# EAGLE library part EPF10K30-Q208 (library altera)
EPF10K30 FLEX 10K family
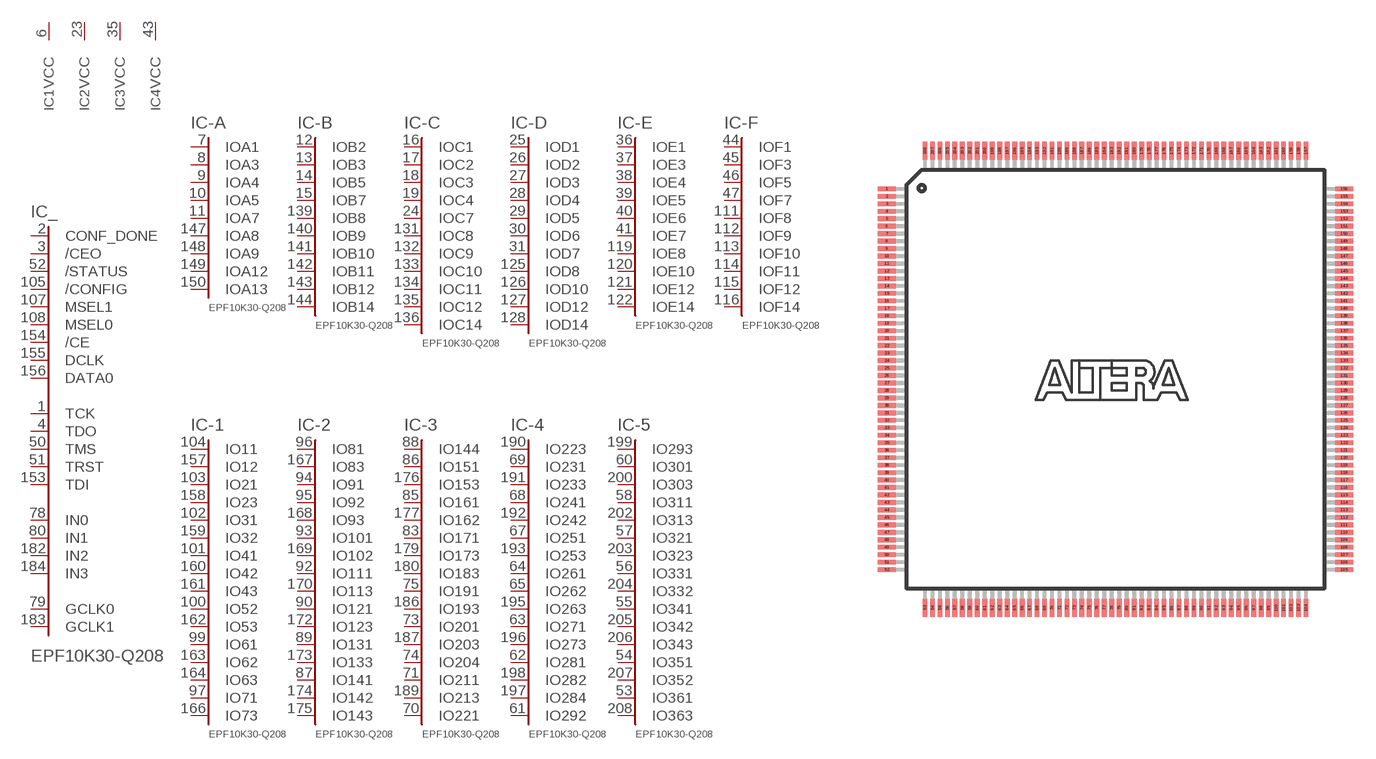
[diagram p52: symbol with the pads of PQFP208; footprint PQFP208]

Designator prefix IC; gates _=100R240C -A=A13-30Q -B=B14-30Q -C=C14-30Q -D=D14-30Q -E=E14-30Q -F=F14-30Q -1=37-30Q -2=143-30Q -3=221-30Q -4=292-30Q -5=363-30Q 1=VCCINT 2=VCCINT 3=VCCINT 4=VCCINT 5=VCCINT 6=VCCINT 7=VCCINT 8=VCCINT 9=VCCINT 10=VCCINT 11=VCCINT 12=VCCINT 13=VCCIO 14=VCCIO 15=VCCIO 16=VCCIO 17=VCCIO 18=VCCIO 19=VCCIO 20=VCCIO 21=VCCIO 22=VCCIO 23=VCCIO 24=VCCIO 25=VCCIO 26=VCCIO 27=GNDINT 28=GNDINT 29=GNDINT 30=GNDINT 31=GNDINT 32=GNDINT 33=GNDINT 34=GNDINT 35=GNDINT 36=GNDIO 37=GNDIO 38=GNDIO 39=GNDIO 40=GNDIO 41=GNDIO 42=GNDIO 43=GNDIO 44=GNDIO 45=GNDIO 46=GNDIO 47=GNDIO

## EPF10K30-Q208 (MPN: EPF10K30EQC208-2N; OC_FARNELL: 1549382; OC_NEWARK: 51R8987)  [PQFP208]
1  _:TCK
2  _:CONF_DONE  in
3  _:/CEO  in
4  _:TDO
5  13:VCCIO  pwr
6  1:VCC  pwr
7  -A:IOA1
8  -A:IOA3
9  -A:IOA4
10  -A:IOA5
11  -A:IOA7
12  -B:IOB2
13  -B:IOB3
14  -B:IOB5
15  -B:IOB7
16  -C:IOC1
17  -C:IOC2
18  -C:IOC3
19  -C:IOC4
20  36:GNDIO  pwr
21  27:GND  pwr
22  14:VCCIO  pwr
23  2:VCC  pwr
24  -C:IOC7
25  -D:IOD1
26  -D:IOD2
27  -D:IOD3
28  -D:IOD4
29  -D:IOD5
30  -D:IOD6
31  -D:IOD7
32  37:GNDIO  pwr
33  28:GND  pwr
34  15:VCCIO  pwr
35  3:VCC  pwr
36  -E:IOE1
37  -E:IOE3
38  -E:IOE4
39  -E:IOE5
40  -E:IOE6
41  -E:IOE7
42  16:VCCIO  pwr
43  4:VCC  pwr
44  -F:IOF1
45  -F:IOF3
46  -F:IOF5
47  -F:IOF7
48  38:GNDIO  pwr
49  29:GND  pwr
50  _:TMS
51  _:TRST
52  _:/STATUS  in
53  -5:IO361
54  -5:IO351
55  -5:IO341
56  -5:IO331
57  -5:IO321
58  -5:IO311
59  39:GNDIO  pwr
60  -5:IO301
61  -4:IO292
62  -4:IO281
63  -4:IO271
64  -4:IO261
65  -4:IO262
66  17:VCCIO  pwr
67  -4:IO251
68  -4:IO241
69  -4:IO231
70  -3:IO221
71  -3:IO211
72  40:GNDIO  pwr
73  -3:IO201
74  -3:IO204
75  -3:IO191
76  5:VCC  pwr
77  6:VCC  pwr
78  _:IN0  in
79  _:GCLK0  in
80  _:IN1  in
81  30:GND  pwr
82  31:GND  pwr
83  -3:IO171
84  18:VCCIO  pwr
85  -3:IO161
86  -3:IO151
87  -2:IO141
88  -3:IO144
89  -2:IO131
90  -2:IO121
91  41:GNDIO  pwr
92  -2:IO111
93  -2:IO101
94  -2:IO91
95  -2:IO92
96  -2:IO81
97  -1:IO71
98  19:VCCIO  pwr
99  -1:IO61
100  -1:IO52
101  -1:IO41
102  -1:IO31
103  -1:IO21
104  -1:IO11
105  _:/CONFIG  in
106  7:VCC  pwr
107  _:MSEL1  in
108  _:MSEL0  in
109  8:VCC  pwr
110  20:VCCIO  pwr
111  -F:IOF8
112  -F:IOF9
113  -F:IOF10
114  -F:IOF11
115  -F:IOF12
116  -F:IOF14
117  9:VCC  pwr
118  21:VCCIO  pwr
119  -E:IOE8
120  -E:IOE10
121  -E:IOE12
122  -E:IOE14
123  32:GND  pwr
124  42:GNDIO  pwr
125  -D:IOD8
126  -D:IOD10
127  -D:IOD12
128  -D:IOD14
129  33:GND  pwr
130  43:GNDIO  pwr
131  -C:IOC8
132  -C:IOC9
133  -C:IOC10
134  -C:IOC11
135  -C:IOC12
136  -C:IOC14
137  10:VCC  pwr
138  22:VCCIO  pwr
139  -B:IOB8
140  -B:IOB9
141  -B:IOB10
142  -B:IOB11
143  -B:IOB12
144  -B:IOB14
145  11:VCC  pwr
146  23:VCCIO  pwr
147  -A:IOA8
148  -A:IOA9
149  -A:IOA12
150  -A:IOA13
151  34:GND  pwr
152  44:GNDIO  pwr
153  _:TDI
154  _:/CE  in
155  _:DCLK  in
156  _:DATA0  in
157  -1:IO12
158  -1:IO23
159  -1:IO32
160  -1:IO42
161  -1:IO43
162  -1:IO53
163  -1:IO62
164  -1:IO63
165  24:VCCIO  pwr
166  -1:IO73
167  -2:IO83
168  -2:IO93
169  -2:IO102
170  -2:IO113
171  45:GNDIO  pwr
172  -2:IO123
173  -2:IO133
174  -2:IO142
175  -2:IO143
176  -3:IO153
177  -3:IO162
178  25:VCCIO  pwr
179  -3:IO173
180  -3:IO183
181  12:VCC  pwr
182  _:IN2  in
183  _:GCLK1  in
184  _:IN3  in
185  35:GND  pwr
186  -3:IO193
187  -3:IO203
188  46:GNDIO  pwr
189  -3:IO213
190  -4:IO223
191  -4:IO233
192  -4:IO242
193  -4:IO253
194  26:VCCIO  pwr
195  -4:IO263
196  -4:IO273
197  -4:IO284
198  -4:IO282
199  -5:IO293
200  -5:IO303
201  47:GNDIO  pwr
202  -5:IO313
203  -5:IO323
204  -5:IO332
205  -5:IO342
206  -5:IO343
207  -5:IO352
208  -5:IO363

## Footprint PQFP208 (pad centres in mm)
Plastic Quad Flat Pack
smd 1.2 x 0.32: 1 -15.3,12.75; 2 -15.3,12.25; 3 -15.3,11.75; 4 -15.3,11.25; 5 -15.3,10.75; 6 -15.3,10.25; 7 -15.3,9.75; 8 -15.3,9.25; 9 -15.3,8.75; 10 -15.3,8.25; 11 -15.3,7.75; 12 -15.3,7.25; 13 -15.3,6.75; 14 -15.3,6.25; 15 -15.3,5.75; 16 -15.3,5.25; 17 -15.3,4.75; 18 -15.3,4.25; 19 -15.3,3.75; 20 -15.3,3.25; 21 -15.3,2.75; 22 -15.3,2.25; 23 -15.3,1.75; 24 -15.3,1.25; 25 -15.3,0.75; 26 -15.3,0.25; 27 -15.3,-0.25; 28 -15.3,-0.75; 29 -15.3,-1.25; 30 -15.3,-1.75; 31 -15.3,-2.25; 32 -15.3,-2.75; 33 -15.3,-3.25; 34 -15.3,-3.75; 35 -15.3,-4.25; 36 -15.3,-4.75; 37 -15.3,-5.25; 38 -15.3,-5.75; 39 -15.3,-6.25; 40 -15.3,-6.75; 41 -15.3,-7.25; 42 -15.3,-7.75; 43 -15.3,-8.25; 44 -15.3,-8.75; 45 -15.3,-9.25; 46 -15.3,-9.75; 47 -15.3,-10.25; 48 -15.3,-10.75; 49 -15.3,-11.25; 50 -15.3,-11.75; 51 -15.3,-12.25; 52 -15.3,-12.75; 105 15.3,-12.75; 106 15.3,-12.25; 107 15.3,-11.75; 108 15.3,-11.25; 109 15.3,-10.75; 110 15.3,-10.25; 111 15.3,-9.75; 112 15.3,-9.25; 113 15.3,-8.75; 114 15.3,-8.25; 115 15.3,-7.75; 116 15.3,-7.25; 117 15.3,-6.75; 118 15.3,-6.25; 119 15.3,-5.75; 120 15.3,-5.25; 121 15.3,-4.75; 122 15.3,-4.25; 123 15.3,-3.75; 124 15.3,-3.25; 125 15.3,-2.75; 126 15.3,-2.25; 127 15.3,-1.75; 128 15.3,-1.25; 129 15.3,-0.75; 130 15.3,-0.25; 131 15.3,0.25; 132 15.3,0.75; 133 15.3,1.25; 134 15.3,1.75; 135 15.3,2.25; 136 15.3,2.75; 137 15.3,3.25; 138 15.3,3.75; 139 15.3,4.25; 140 15.3,4.75; 141 15.3,5.25; 142 15.3,5.75; 143 15.3,6.25; 144 15.3,6.75; 145 15.3,7.25; 146 15.3,7.75; 147 15.3,8.25; 148 15.3,8.75; 149 15.3,9.25; 150 15.3,9.75; 151 15.3,10.25; 152 15.3,10.75; 153 15.3,11.25; 154 15.3,11.75; 155 15.3,12.25; 156 15.3,12.75
smd 0.32 x 1.2: 53 -12.75,-15.3; 54 -12.25,-15.3; 55 -11.75,-15.3; 56 -11.25,-15.3; 57 -10.75,-15.3; 58 -10.25,-15.3; 59 -9.75,-15.3; 60 -9.25,-15.3; 61 -8.75,-15.3; 62 -8.25,-15.3; 63 -7.75,-15.3; 64 -7.25,-15.3; 65 -6.75,-15.3; 66 -6.25,-15.3; 67 -5.75,-15.3; 68 -5.25,-15.3; 69 -4.75,-15.3; 70 -4.25,-15.3; 71 -3.75,-15.3; 72 -3.25,-15.3; 73 -2.75,-15.3; 74 -2.25,-15.3; 75 -1.75,-15.3; 76 -1.25,-15.3; 77 -0.75,-15.3; 78 -0.25,-15.3; 79 0.25,-15.3; 80 0.75,-15.3; 81 1.25,-15.3; 82 1.75,-15.3; 83 2.25,-15.3; 84 2.75,-15.3; 85 3.25,-15.3; 86 3.75,-15.3; 87 4.25,-15.3; 88 4.75,-15.3; 89 5.25,-15.3; 90 5.75,-15.3; 91 6.25,-15.3; 92 6.75,-15.3; 93 7.25,-15.3; 94 7.75,-15.3; 95 8.25,-15.3; 96 8.75,-15.3; 97 9.25,-15.3; 98 9.75,-15.3; 99 10.25,-15.3; 100 10.75,-15.3; 101 11.25,-15.3; 102 11.75,-15.3; 103 12.25,-15.3; 104 12.75,-15.3; 157 12.75,15.3; 158 12.25,15.3; 159 11.75,15.3; 160 11.25,15.3; 161 10.75,15.3; 162 10.25,15.3; 163 9.75,15.3; 164 9.25,15.3; 165 8.75,15.3; 166 8.25,15.3; 167 7.75,15.3; 168 7.25,15.3; 169 6.75,15.3; 170 6.25,15.3; 171 5.75,15.3; 172 5.25,15.3; 173 4.75,15.3; 174 4.25,15.3; 175 3.75,15.3; 176 3.25,15.3; 177 2.75,15.3; 178 2.25,15.3; 179 1.75,15.3; 180 1.25,15.3; 181 0.75,15.3; 182 0.25,15.3; 183 -0.25,15.3; 184 -0.75,15.3; 185 -1.25,15.3; 186 -1.75,15.3; 187 -2.25,15.3; 188 -2.75,15.3; 189 -3.25,15.3; 190 -3.75,15.3; 191 -4.25,15.3; 192 -4.75,15.3; 193 -5.25,15.3; 194 -5.75,15.3; 195 -6.25,15.3; 196 -6.75,15.3; 197 -7.25,15.3; 198 -7.75,15.3; 199 -8.25,15.3; 200 -8.75,15.3; 201 -9.25,15.3; 202 -9.75,15.3; 203 -10.25,15.3; 204 -10.75,15.3; 205 -11.25,15.3; 206 -11.75,15.3; 207 -12.25,15.3; 208 -12.75,15.3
